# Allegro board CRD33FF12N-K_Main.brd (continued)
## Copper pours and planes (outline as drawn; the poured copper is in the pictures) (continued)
DC_N on ART04: 146.04,60.5 147.96,62.41 171.24,62.41 174.21,65.38 174.47,65.38 174.42,65.33 174.42,63.71 174.87,63.25 188.35,63.25 195.6,56.01 270.64,56.01 277.67,48.98 362.08,48.98 389.73,76.63 405.51,76.63 408.55,79.68 408.55,172.67 404.46,176.77 304.87,176.77 296.3,168.2 185.16,168.2 185.96,169 185.96,169.83 184.97,170.83 175.37,170.83 172.87,168.32 159.18,168.32 155.06,164.2 147.48,164.2 145.52,166.16 145.52,181.71 155.94,192.13 155.94,192.16 161.33,197.55 220.87,197.55 222.85,199.52 457.53,199.52 460.95,196.1 460.95,182.88 454.64,176.56 440.92,176.56 437.64,173.28 437.64,46.91 427.08,36.35 393.79,36.35 382.36,24.93 371.32,13.88 371.14,13.7 245.13,13.7 220.4,38.43 146.51,38.43 146.04,38.9
DC_N on ART05: 174.76,197.55 220.87,197.55 222.85,199.52 457.53,199.52 460.95,196.1 460.95,182.88 454.64,176.56 440.92,176.56 437.64,173.28 437.64,46.91 427.08,36.35 393.79,36.35 372.09,14.66 312.29,14.66 311.34,13.7 245.13,13.7 220.4,38.43 146.51,38.43 146.04,38.9 146.04,66.48 147.1,67.53 150.95,67.53 155.19,63.29 174.84,63.29 174.87,63.25 177.04,63.25 178.04,62.26 186.82,62.26 187.82,63.25 188.34,63.25 195.58,56.02 270.78,56.02 277.82,48.98 362.08,48.98 389.73,76.63 405.51,76.63 408.55,79.68 408.55,172.67 404.46,176.77 304.87,176.77 296.3,168.2 211.25,168.2 206.11,163.06 194.59,163.06 194.36,162.82 184.54,162.82 179.04,168.32 159.18,168.32 155.06,164.2 155.02,164.2 153.9,163.07 146.69,163.07 145.52,164.24 145.52,181.71 155.94,192.13 155.94,192.16 156.61,192.83 170.04,192.83
DC_N on ART05: 460.85,190.57 460.85,179.69 458.96,177.8 443.55,177.8 433.75,168 433.75,42.88 427.75,36.88 416.46,36.88 416.45,36.9 413.97,36.9 408.57,42.3 408.57,172.76 403.72,177.6 403.72,187.45 408.18,191.91 459.51,191.91
DRV_COM1 on BOTTOM (solid shape): 84.36,160.66 84.36,159.18 84.11,158.93 81.8,158.93 81.6,159.12 81.6,159.55 81.58,159.57 81.58,160.66 81.69,160.76 84.26,160.76
DRV_COM1 on BOTTOM (solid shape): 69,174.25 69,172.62 69.65,171.98 69.65,170.69 69.9,170.44 69.9,168.05 69.48,167.63 69.48,164.9 69.84,164.55 70.68,164.55 70.69,164.55 74.26,164.55 74.5,164.3 74.5,162.99 74.89,162.6 74.89,162.17 74.7,161.98 73.77,161.98 73.56,162.19 73.56,162.87 73.44,162.99 69.19,162.99 67.65,164.52 67.65,167.66 68.24,168.25 68.24,170.04 67.19,171.09 67.19,172.43 67.48,172.72 67.48,174.38 67.73,174.64 68.62,174.64
DRV_COM1 on ART05: 123.45,154.36 123.17,154.08 121.6,154.08 121.19,153.67 121.19,151.51 121.11,151.43 114.56,151.43 111.92,154.08 103.33,154.08 102.69,153.43 100.38,153.43 100.13,153.19 100.13,151.43 99.98,151.28 93.54,151.28 91.4,153.43 84.6,153.43 84.54,153.49 80.86,153.49 80.42,153.06 80.42,151.76 79.84,151.18 73.87,151.18 73.29,151.76 73.29,157.94 76.49,161.14 76.64,161.14 79.74,164.24 86.62,164.24 90.03,160.83 119.92,160.83 123.45,157.3 ; 1 cut-out
DRV_COM2 on BOTTOM (solid shape): 168.93,161.19 168.93,160.27 168.79,160.14 167.76,160.14 167.65,160.02 167.65,159.82 167.8,159.66 168.28,159.66 168.36,159.59 168.36,159 168.18,158.83 166.86,158.83 166.6,159.08 166.6,161.15 166.73,161.27 168.85,161.27
DRV_COM2 on BOTTOM (solid shape): 189.99,169.42 189.99,168.41 190,168.4 190,167 184.91,161.92 182.69,161.92 182.13,162.48 179.87,162.48 179.44,162.04 179.44,159.86 179.38,159.8 178,159.8 177.61,160.19 177.61,163.5 178.05,163.95 182.56,163.95 182.94,164.33 185.3,164.33 188.35,167.38 188.35,169.41 188.5,169.56 189.86,169.56
DRV_COM2 on ART05: 191.27,153.01 190.91,152.65 190.91,151.49 190.74,151.31 184.74,151.31 183.04,153.01 170.24,153.01 169.68,152.45 169.68,151.41 169.22,150.95 163.18,150.95 160.69,153.44 147.86,153.44 147.56,153.14 147.56,151.46 147.38,151.28 141.1,151.28 140.8,151.59 140.8,158.01 142.98,160.2 159.37,160.2 164.22,165.05 174.84,165.05 181.57,158.32 191.07,158.32 193.43,155.96 193.43,153.34 193.1,153.01
DRV_COM3 on BOTTOM (solid shape): 179.41,73.32 179.41,73.05 179.18,72.82 178.98,72.82 178.93,72.77 178.93,72.67 179.03,72.57 180.45,72.57 180.55,72.47 180.55,71.63 180.48,71.56 178.15,71.56 178.07,71.64 178.07,73.3 178.22,73.45 179.28,73.45
DRV_COM3 on BOTTOM (solid shape): 191.47,64.25 191.47,62.3 191.89,61.88 194.45,61.88 194.45,61.95 194.61,61.95 194.99,62.33 196.77,62.33 197.66,61.44 199.98,61.44 202.6,58.82 202.6,57.68 202.33,57.42 201.35,57.42 200.99,57.78 200.99,58.24 199.31,59.92 194.86,59.92 194.61,60.17 194.59,60.17 194.48,60.28 190.1,60.28 189.93,60.45 189.93,64.29 189.96,64.32 191.4,64.32
DRV_COM3 on ART05: 185.71,78.84 183.52,81.03 177.05,81.03 176.82,80.8 176.82,79.5 176.41,79.1 174.45,79.1 171.48,76.12 164.42,76.12 162.67,77.88 162.67,80.09 161.75,81 155.4,81 155.2,80.8 155.2,78.94 154.82,78.56 151.95,78.56 151.65,78.26 151.65,75.49 152.89,74.24 173.08,74.24 176.11,71.22 176.11,67.59 178.95,64.74 185.5,64.74 194.8,74.04 202.04,74.04 202.67,74.68 202.67,80.87 202.47,81.08 196.35,81.08 196.1,80.82 196.1,79.38 195.66,78.94 193.43,78.94 191.45,76.96 186.42,76.96 185.71,77.67
DRV_COM4 on BOTTOM (solid shape): 84.63,69.55 88.98,69.55 89.17,69.37 89.17,65.68 88.97,65.49 87.48,65.49 87.41,65.56 87.41,67.88 87.33,67.97 84.15,67.97 83.84,67.65 83,67.65 82.57,68.09 81.32,68.09 80.12,66.89 75.94,66.89 74.26,68.57 74.26,69.64 74.66,70.04 75.59,70.04 75.98,69.66 75.98,68.61 76.58,68.01 79.02,68.01 80.59,69.58 82.41,69.58 83,70.17 84.02,70.17
DRV_COM4 on ART05: 124.32,78.44 115.68,78.44 114.84,79.27 114.84,80.82 114.59,81.08 107.5,81.08 107.27,80.85 107.27,79.5 106.94,79.17 104.81,79.17 104.07,78.44 102.83,78.44 101.53,77.14 94.78,77.14 92.86,79.06 92.86,80.05 91.88,81.03 85.83,81.03 85.63,80.82 85.63,79.17 85.17,78.71 84.44,78.71 83.8,78.08 83.8,74.93 84.89,73.84 100.72,73.84 107.78,66.78 113.42,66.78 119.57,72.92 132.11,72.92 133.76,74.57 133.76,80.62 133.51,80.87 127.44,80.87 127.21,80.64 127.21,79.35 126.86,78.99 124.87,78.99 ; 1 cut-out
DRV_COM5 on BOTTOM (solid shape): 236.89,158.63 236.73,158.47 234.67,158.47 234.43,158.71 234.43,160.32 234.48,160.37 236.89,160.37
DRV_COM5 on BOTTOM (solid shape): 253.52,168.46 253.52,164.14 253.14,163.76 253.14,161.22 253.65,160.71 253.95,160.71 253.95,160.64 255.5,160.64 255.68,160.46 255.68,158.93 255.55,158.81 251.87,158.81 251.56,159.12 251.56,160.79 251.49,160.79 251.49,161.65 251.56,161.65 251.56,163.34 251.49,163.34 251.49,163.5 251.11,163.89 251.11,165.66 252,166.55 252,168.33 252.38,168.71 253.27,168.71
DRV_COM6 on BOTTOM (solid shape): 234.57,72.97 234.57,72.67 234.62,72.61 235.35,72.61 235.45,72.52 235.45,71.77 235.39,71.7 235.1,71.7 235.08,71.72 234.45,71.72 234.4,71.72 233.68,71.72 233.64,71.75 232.99,71.75 232.94,71.8 232.94,72.44 233.11,72.61 233.55,72.61 233.56,72.62 233.56,72.88 233.74,73.06 234.47,73.06
DRV_COM6 on BOTTOM (solid shape): 250.97,66.47 250.97,65.19 250.78,64.99 248.17,64.99 247.99,64.81 247.99,62.46 248.37,62.08 248.37,57.76 247.92,57.32 247.42,57.32 246.84,57.89 246.84,59.67 245.96,60.56 245.96,62.34 246.34,62.72 246.34,62.88 246.41,62.88 246.41,65.43 246.41,65.43 246.41,66.36 246.41,66.36 246.41,66.69 246.56,66.84 250.61,66.84
DRV_Q1_+15V on BOTTOM (solid shape): 72.01,173.86 72.01,169.06 73.23,167.85 76.56,167.85 76.78,167.64 76.78,165.96 76.67,165.85 71.03,165.85 71.02,165.84 70.18,165.84 70.05,165.97 70.05,167.25 70.47,167.67 70.47,170.59 70.22,170.84 70.22,172.15 69.88,172.49 69.88,174.23 70.27,174.62 71.25,174.62
DRV_Q1_-3V on BOTTOM (solid shape): 66.44,174.57 66.44,173.18 66.62,173 66.62,168.13 66.39,167.9 65.07,167.9 64.81,168.16 64.81,174.51 65.16,174.85 66.16,174.85
DRV_Q2_+15V on BOTTOM (solid shape): 187.03,169.55 187.18,169.55 187.33,169.39 187.33,167.38 184.83,164.88 182.51,164.88 182.16,165.23 178.16,165.23 178.06,165.32 178.06,166.66 178.25,166.86 180.45,166.86 180.47,166.88 180.9,166.88 180.91,166.87 184.28,166.87 185.84,168.43 185.84,169.35 186.06,169.57 187.01,169.57
DRV_Q2_-3V on BOTTOM (solid shape): 192.4,169.49 192.4,169.11 192.41,169.1 192.41,168.6 192.41,168.6 192.41,165.79 187.51,160.9 185.99,159.38 180.79,159.38 180.71,159.45 180.71,161.59 180.76,161.64 182.6,161.64 182.83,161.41 185.36,161.41 190.92,166.97 190.92,169.46 191,169.55 192.35,169.55
DRV_Q3_+15V on BOTTOM (solid shape): 196.89,58.9 199.56,58.9 200.07,58.39 200.07,57.89 199.56,57.38 190.12,57.38 190.01,57.49 190.01,58.91 190.1,59.01 194.52,59.01 194.85,59.33 196.46,59.33
DRV_Q3_-3V on BOTTOM (solid shape): 193.6,66.99 193.6,65.3 194.03,64.87 199.95,64.87 205.25,59.57 205.25,57.75 204.85,57.35 203.74,57.35 203.46,57.63 203.46,59.05 199.67,62.84 194.48,62.84 194.22,62.58 192.87,62.58 192.74,62.71 192.74,64.68 192.74,64.68 192.74,67.04 192.96,67.26 193.33,67.26
DRV_Q4_+15V on BOTTOM (solid shape): 88.82,72.01 88.82,70.44 88.71,70.33 84.5,70.33 84.16,70.68 80.24,70.68 77.93,68.36 77.41,68.36 76.86,68.92 76.86,69.88 79.21,72.24 88.59,72.24
DRV_Q4_-3V on BOTTOM (solid shape): 73.43,69.67 73.43,68.43 75.57,66.29 80.69,66.29 81.5,67.1 84.24,67.1 84.25,67.09 84.46,67.31 86.09,67.31 86.2,67.19 86.2,65.43 86.04,65.27 82.09,65.27 81.49,64.67 75.18,64.67 75.15,64.69 74.83,64.69 71.79,67.72 71.79,69.81 72.05,70.06 73.03,70.06
DRV_Q5_+15V on BOTTOM (solid shape): 251.11,168.46 251.11,167.06 250.6,166.55 250.6,164.01 250.34,163.76 250.34,159.06 250.09,158.81 248.69,158.81 248.57,158.93 248.57,167.57 249.71,168.71 250.85,168.71
DRV_Q5_-3V on BOTTOM (solid shape): 256.06,168.46 256.06,162.11 255.81,161.85 254.03,161.85 253.9,161.98 253.9,164.11 253.98,164.11 253.98,164.93 253.9,164.93 253.9,165.16 254.54,165.79 254.54,168.46 255.04,168.97 255.55,168.97
DRV_Q6_+15V on BOTTOM (solid shape): 245.19,68.79 245.19,62.46 245.45,62.21 245.45,60.13 245.96,59.62 245.96,57.76 245.5,57.31 244.76,57.31 244.18,57.89 244.18,60.28 243.42,61.05 243.42,68.84 243.54,68.96 245.02,68.96
DRV_Q6_-3V on BOTTOM (solid shape): 250.91,57.76 250.4,57.26 249.89,57.26 249.38,57.76 249.38,60.43 249,60.81 249,63.47 249.18,63.65 250.91,63.65
FAN_12V on TOP: 11.8,44.25 11.8,172.33 12.73,173.26 12.73,178.92 12.12,179.53 4.61,179.53 4.1,180.04 4.1,186.31 7.42,189.64 17.86,189.64 19.68,187.82 19.68,16.84 15.81,12.98 11.28,12.98 8.94,15.32 8.94,24.29 8.97,24.31 8.97,38.96 9.94,39.93 9.94,42.38
FAN_12V on BOTTOM: 11.8,44.25 11.8,172.33 12.73,173.26 12.73,178.92 12.12,179.53 4.61,179.53 4.1,180.04 4.1,186.31 7.42,189.64 17.86,189.64 19.68,187.82 19.68,16.84 15.84,13 11.26,13 8.94,15.32 8.94,24.29 8.97,24.31 8.97,38.96 9.94,39.93 9.94,42.38
FAN_12V on GND02: 11.8,44.25 11.8,172.33 12.73,173.26 12.73,178.92 12.12,179.53 4.61,179.53 4.1,180.04 4.1,186.31 7.42,189.64 17.86,189.64 19.68,187.82 19.68,16.84 15.81,12.98 11.26,12.98 8.94,15.29 8.94,24.29 8.97,24.31 8.97,38.96 9.94,39.93 9.94,42.38
FAN_12V on ART03: 11.8,44.25 11.8,172.33 12.73,173.26 12.73,178.92 12.12,179.53 4.61,179.53 4.1,180.04 4.1,186.31 7.42,189.64 17.86,189.64 19.68,187.82 19.68,16.84 15.85,13.01 11.17,13.01 8.94,15.24 8.94,24.29 8.97,24.31 8.97,38.96 9.94,39.93 9.94,42.38
FAN_12V on ART04: 11.8,44.25 11.8,172.33 12.73,173.26 12.73,178.92 12.12,179.53 4.61,179.53 4.1,180.04 4.1,186.31 7.42,189.64 17.86,189.64 19.68,187.82 19.68,16.84 15.84,13 11.21,13 8.94,15.27 8.94,24.29 8.97,24.31 8.97,38.96 9.94,39.93 9.94,42.38
FAN_12V on ART05: 11.8,44.25 11.8,172.33 12.73,173.26 12.73,178.92 12.12,179.53 4.61,179.53 4.1,180.04 4.1,186.31 7.42,189.64 17.86,189.64 19.68,187.82 19.68,16.84 15.94,13.1 11.13,13.1 8.94,15.29 8.94,24.29 8.97,24.31 8.97,38.96 9.94,39.93 9.94,42.38
FAN_GND on TOP: 1.91,6.92 22.61,6.92 30.11,14.41 30.11,42.04 40.52,52.45 40.52,175.42 21.43,194.51 4.48,194.51 2.17,192.2 2.17,176.1 4.99,173.28 4.99,162.62 1.66,159.29 1.66,7.17
FAN_GND on BOTTOM: 1.91,6.92 20.45,6.92 27.44,13.9 27.44,45.21 40.52,58.29 40.52,175.42 21.43,194.51 4.48,194.51 2.17,192.2 2.17,176.1 4.99,173.28 4.99,162.62 1.66,159.29 1.66,7.17
FAN_GND on GND02: 1.91,6.92 21.91,6.92 28.58,13.59 28.58,47.12 40.52,59.05 40.52,175.42 21.43,194.51 4.48,194.51 2.17,192.2 2.17,176.1 4.99,173.28 4.99,162.62 1.66,159.29 1.66,7.17
FAN_GND on ART03: 1.91,6.92 20.96,6.92 27.95,13.9 27.95,46.74 40.52,59.31 40.52,175.42 21.43,194.51 4.48,194.51 2.17,192.2 2.17,176.1 4.99,173.28 4.99,162.62 1.66,159.29 1.66,7.17
FAN_GND on ART04: 1.91,6.92 20.45,6.92 27.31,13.78 27.31,46.61 40.52,59.82 40.52,175.42 21.43,194.51 4.48,194.51 2.17,192.2 2.17,176.1 4.99,173.28 4.99,162.62 1.66,159.29 1.66,7.17
FAN_GND on ART05: 1.91,6.92 20.33,6.92 27.44,14.03 27.44,46.48 40.52,59.56 40.52,175.42 21.43,194.51 4.48,194.51 2.17,192.2 2.17,176.1 4.99,173.28 4.99,162.62 1.66,159.29 1.66,7.17
GGND on BOTTOM (solid shape): 58.97,174.11 58.97,164.84 58.72,164.58 57.35,164.58 57.22,164.71 57.22,166.33 56.81,166.74 56.81,171.95 57.19,172.33 57.19,174.36 57.57,174.74 58.34,174.74
GGND on BOTTOM (solid shape): 199.8,177.29 199.8,175.66 199.82,175.66 199.82,175.49 200.07,175.24 200.07,168.34 199.91,168.19 198.06,168.19 197.91,168.34 197.91,177.14 198.16,177.4 199.69,177.4
GGND on BOTTOM (solid shape): 258.53,58.58 258.53,56.55 258.91,56.17 258.91,50.96 258.66,50.71 258.66,50.54 258.64,50.54 258.64,48.91 258.53,48.81 257,48.81 256.75,49.06 256.75,58.33 257.39,58.97 258.15,58.97
GGND on BOTTOM (solid shape): 263.79,177.24 263.79,175.62 263.81,175.62 263.81,175.44 264.06,175.19 264.06,169.98 263.68,169.6 263.68,167.57 263.3,167.19 262.54,167.19 261.9,167.82 261.9,177.09 262.16,177.35 263.68,177.35
GGND on BOTTOM (solid shape): 212.89,58.65 212.89,56.13 213.17,55.85 213.17,51.06 214.41,49.82 217.43,49.82 217.5,49.75 217.5,48.3 217.42,48.22 212.61,48.22 210.79,50.04 210.79,58.79 211,59 212.54,59
GGND on BOTTOM (solid shape): 66.01,69.96 66.01,60.84 63.74,58.56 57.7,58.56 57.19,59.08 57.19,59.58 57.56,59.95 63.38,59.95 64.12,60.69 64.12,62.31 64.1,62.31 64.1,62.49 63.85,62.74 63.85,67.95 63.87,67.97 63.87,69.85 64.21,70.19 65.77,70.19
MID_N on TOP (solid shape): outline of 95 points within 74.74,81.33 210.43,113.69
MID_N on BOTTOM (solid shape): outline of 112 points within 74.74,81.33 247.22,113.69
MID_N on GND02 (solid shape): outline of 95 points within 74.74,81.33 210.43,113.69
MID_N on ART03 (solid shape): outline of 94 points within 74.74,81.33 210.43,113.69
MID_N on ART04 (solid shape): outline of 122 points within 152.76,65.37 191.32,86.7
MID_N on ART04 (solid shape): outline of 113 points within 74.74,81.33 247.22,113.69
MID_N on ART05 (solid shape): outline of 114 points within 74.74,81.33 247.22,113.69
MID_P on TOP (solid shape): outline of 119 points within 72.82,118.46 210.64,150.83
MID_P on BOTTOM (solid shape): outline of 119 points within 72.82,118.46 254.23,150.88
MID_P on GND02 (solid shape): outline of 122 points within 72.82,118.46 210.64,150.83
MID_P on ART03 (solid shape): outline of 113 points within 72.82,118.46 210.64,150.83
MID_P on ART04 (solid shape): outline of 135 points within 72.82,118.46 254.23,150.88
MID_P on ART05 (solid shape): outline of 137 points within 72.82,118.46 254.23,150.88
MID_P on ART04: 123.03,151.38 114.74,151.38 112.66,153.46 105.57,153.46 105.05,152.94 105.05,145.95 104.44,145.34 103.53,145.34 102.77,146.1 102.77,150.68 102.19,151.26 93.64,151.26 91.67,153.23 91.65,153.23 90.55,154.33 86.33,154.33 86.33,155.28 88.94,157.89 88.94,159.54 88.97,159.58 88.97,160.59 89.67,161.29 120.28,161.29 123.92,157.65 123.92,152.26
NETC43_2 on GND02: 219.97,199.76 182.71,199.76 181.67,200.81 181.67,205.06 182.35,205.75 219.92,205.75 220.45,205.22 220.45,200.25
NETC43_2 on GND02: 103.55,199 67,199 66.31,199.69 66.31,204.6 66.7,204.99 103.5,204.99 104.03,204.45 104.03,199.48
NETC43_2 on ART03: 218.97,199.76 158.46,199.76 157.33,198.63 63.8,198.63 62.6,199.83 62.6,204.13 64.23,205.75 219.92,205.75 220.45,205.22 220.45,201.25
NETC43_2 on ART04: 219.08,199.76 158.46,199.76 157.37,198.67 63.82,198.67 62.6,199.88 62.6,204.13 64.23,205.75 219.92,205.75 220.45,205.22 220.45,201.14
NETC49_2 on ART04: 64.63,24.7 65.95,23.38 208.93,23.38 209.99,24.44 209.99,35.84 209.11,36.72 66.46,36.72 64.63,34.9
NETC49_2 on ART05: 64.63,24.7 65.95,23.38 208.93,23.38 209.96,24.41 209.96,35.83 209.07,36.72 66.46,36.72 64.63,34.9 ; 1 cut-out
NETC86_1 on BOTTOM (solid shape): 56.3,174.36 56.3,166.83 55.93,166.45 55.93,163.86 56.01,163.78 56.01,162.13 55.92,162.04 54.27,162.04 54.02,162.3 54.02,174.23 54.53,174.74 55.92,174.74
NETC103_1 on BOTTOM (solid shape): 202.86,179.68 202.86,168.21 202.74,168.08 200.89,168.08 200.58,168.39 200.58,174.92 201,175.34 201,179.85 201.09,179.94 202.61,179.94
NETC112_1 on BOTTOM (solid shape): 215.6,58.76 215.6,53.1 215.82,52.88 220.08,52.88 220.16,52.8 220.16,51.26 220.01,51.1 214.16,51.1 213.8,51.47 213.8,56.18 213.72,56.26 213.72,58.67 213.99,58.93 215.42,58.93
NETC121_1 on BOTTOM (solid shape): 266.85,179.63 266.85,167.7 266.35,167.19 264.95,167.19 264.57,167.57 264.57,175.04 264.95,175.42 264.95,178.08 264.86,178.16 264.86,179.78 264.97,179.89 266.6,179.89
NETC130_1 on BOTTOM (solid shape): 63.34,69.71 63.34,62.71 62.96,62.34 62.96,60.62 62.88,60.53 61.47,60.53 61.47,60.54 59.01,60.54 58.97,60.57 58.97,61.95 59.1,62.08 60.99,62.08 61.34,62.43 61.34,69.85 61.55,70.07 62.99,70.07
NETC139_1 on BOTTOM (solid shape): 261.7,58.46 261.7,46.52 261.45,46.27 259.93,46.27 259.71,46.48 259.71,48 259.67,48 259.67,48.84 259.8,48.84 259.8,50.54 259.59,50.54 259.42,50.71 259.42,58.58 259.8,58.97 261.2,58.97
NETL1_1 on ART04 (solid shape): 402.75,171.26 402.75,167.66 402.74,167.64 402.74,147.27 401.56,146.1 315.44,146.1 313.68,147.86 313.68,171.8 314.2,172.31 401.69,172.31
NETL1_1 on ART05 (solid shape): 402.75,171.26 402.75,167.66 402.74,167.64 402.74,147.27 401.56,146.1 315.44,146.1 313.68,147.86 313.68,171.8 314.2,172.31 401.69,172.31
NETL1_1 on TOP, ART03: 402.74,147.27 401.56,146.1 315.44,146.1 313.68,147.86 313.68,171.8 314.2,172.31 401.69,172.31 402.75,171.26 402.75,167.66 402.74,167.64
NETL1_1 on BOTTOM: 402.79,167.62 402.79,147.25 401.59,146.05 315.42,146.05 313.63,147.84 313.63,171.82 314.18,172.36 401.71,172.36 402.8,171.28 402.8,167.64
NETL1_1 on GND02: 401.54,146.15 402.69,147.29 402.69,167.67 402.7,167.68 402.7,171.23 401.67,172.26 314.22,172.26 313.74,171.78 313.74,147.88 315.46,146.15
NETL1_2 on BOTTOM (solid shape): 360.13,139.98 360.13,89.95 355.91,85.72 318.14,85.72 314.24,89.62 314.24,139.41 315.65,140.82 359.3,140.82
NETL1_2 on GND02 (solid shape): 360.13,139.98 360.13,89.95 355.91,85.72 318.14,85.72 314.24,89.62 314.24,139.41 315.65,140.82 359.3,140.82
NETL1_2 on ART03 (solid shape): 360.13,139.98 360.13,89.95 355.91,85.72 318.14,85.72 314.24,89.62 314.24,139.41 315.65,140.82 359.3,140.82
NETL1_2 on ART04 (solid shape): 360.13,139.98 360.13,89.95 355.91,85.72 318.14,85.72 314.24,89.62 314.24,139.41 315.65,140.82 359.3,140.82
NETL1_2 on ART05 (solid shape): 360.13,139.98 360.13,89.95 355.91,85.72 318.14,85.72 314.24,89.62 314.24,139.41 315.65,140.82 359.3,140.82
NETL1_2 on TOP: 360.64,89.74 360.64,140.19 359.51,141.33 315.44,141.33 313.74,139.62 313.74,89.41 317.93,85.22 356.12,85.22
NETL2_1 on TOP (solid shape): 360.78,76.53 360.78,56.35 359.16,54.74 281.31,54.74 279.03,57.02 279.03,75.82 280.68,77.47 359.84,77.47
NETL2_1 on BOTTOM (solid shape): 360.78,76.53 360.78,56.35 359.16,54.74 281.31,54.74 279.03,57.02 279.03,75.44 281.06,77.47 359.84,77.47
NETL2_1 on GND02 (solid shape): 360.78,76.53 360.78,56.35 359.16,54.74 281.06,54.74 279.03,56.77 279.03,75.95 280.55,77.47 359.84,77.47
NETL2_1 on ART03 (solid shape): 360.78,76.53 360.78,56.35 359.16,54.74 280.93,54.74 279.03,56.64 279.03,75.95 280.55,77.47 359.84,77.47
NETL2_1 on ART04 (solid shape): 360.78,76.53 360.78,56.35 359.16,54.74 281.31,54.74 279.03,57.02 279.03,75.82 280.68,77.47 359.84,77.47
NETL2_1 on ART05 (solid shape): 360.78,76.53 360.78,56.35 359.16,54.74 281.19,54.74 279.03,56.9 279.03,76.2 280.3,77.47 359.84,77.47
NETL2_3 on TOP (solid shape): 406.19,93.8 406.19,36.27 400.45,30.53 400.45,19.53 397.94,17.02 376.39,17.02 371.44,21.97 371.44,93.71 373.16,95.43 381.68,95.43 381.74,95.48 404.51,95.48
NETL2_3 on BOTTOM: 376.09,17.25 371.39,21.95 371.39,93.73 373.14,95.48 381.66,95.48 381.71,95.53 404.53,95.53 406.24,93.82 406.24,39.98 400.5,34.24 400.43,34.17 400.43,22 398.26,19.83 395.68,17.25
NETL2_3 on GND02: 395.6,17.07 400.53,22 400.53,34.37 406.14,39.98 406.14,93.78 404.49,95.43 381.76,95.43 381.71,95.38 373.18,95.38 371.49,93.69 371.49,21.99 376.42,17.07
VA+5V on TOP (solid shape): 210.79,16.15 210.79,14 210.41,13.61 206.47,13.61 205.33,14.76 200.38,14.76 198.34,12.73 194.91,12.73 194.79,12.85 194.79,16.28 195.3,16.79 210.15,16.79
VA+5V on BOTTOM (solid shape): 285.81,11.21 286.44,11.21 287.46,10.19 289.32,10.19 289.42,10.1 289.42,10.05 289.42,10.04 289.42,9.36 289.25,9.18 287.33,9.18 286.96,8.82 286.96,5.33 287.31,4.99 289.31,4.99 289.37,4.93 289.37,4.07 289.28,3.98 287.29,3.98 286.96,3.66 286.96,1.73 286.76,1.52 284.91,1.52 284.57,1.86 284.57,10.88 284.58,10.89 284.58,11.06 284.73,11.21 285.8,11.21
VA+5V on ART04: 286.79,6.27 275.36,6.27 273.83,7.8 269.9,7.8 269.26,7.16 269.26,6.27 268.63,5.64 267.48,5.64 267.1,6.02 267.1,7.54 269.39,9.83 285.77,9.83 287.04,8.56 287.04,6.53

Small or netless copper shapes (teardrops, artwork), in the pictures only: 1 on GND02

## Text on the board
BOTTOM: ARTWORK BOTTOM
Board Geometry/Soldermask Bottom: SOLDERMASK BOTTOM
Package Geometry/Pastemask Bottom: PASTEMASK BOTTOM
Ref Des/Silkscreen Bottom: SILKSCREEN BOTTOM | DC- | DC+ | L2 | L1 | ACL | ACN(DCN)
TOP: ARTWORK TOP
Board Geometry/Soldermask Top: SOLDERMASK TOP
Package Geometry/Pastemask Top: PASTEMASK TOP
Ref Des/Silkscreen Top: CRD33FF12N-K_Main_V1.0 | 2025W11 | SILKSCREEN TOP | T | M | DC+ | DC- | DC_N(H) | DC_N(L) | ACN_(DCN) | ACL
GND02: ARTWORK LAYER02
ART03: ARTWORK LAYER03
ART04: ARTWORK LAYER04
ART05: ARTWORK LAYER05
DIMENSION: FAB DRAWING
ASSEMBLY_TOP: PRIMARY SIDE
ASSEMBLY_BOTTOM: SECONDARY SIDE
User.28: FIGURE | FINISHED_SIZE | 12.0 | 32.0 | 40.0 | 41.0 | 47.0 | 55.0 | 86.0 | 87.0 | 122.0 | 129.921 | 79.0x53.0 | 80.0x60.0 | 118.0x32.0 | 138.0x32.0 | 452.756x145.669 | 500.0x158.0 | ROTATION | - | 0.000 | 90.000 | DRILL CHART: TOP to BOTTOM | ALL UNITS ARE IN MILS | TOLERANCE_DRILL | +0.0/-0.0 | +3.0/-3.0 | PLATED | NON-PLATED | QTY | 618 | 4 | 24 | 5 | 45 | 12 | 2 | 18 | 16 | 8 | 32 | 17 | 48 | 1
